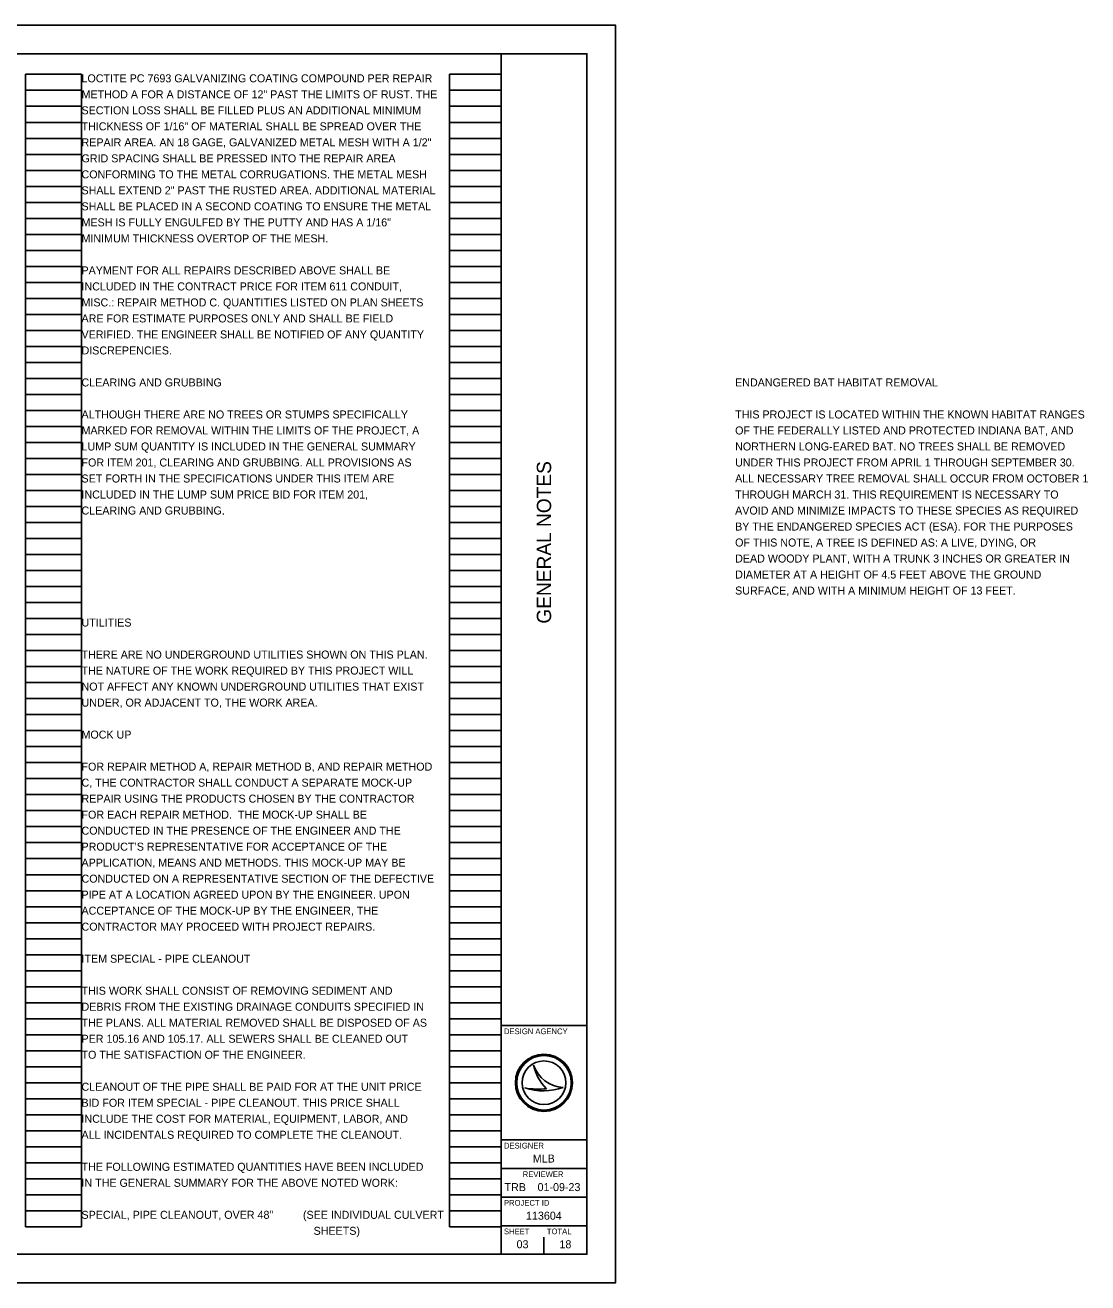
# Model space of a CAD drawing. Extents: x 0 to 42.3, y -7.4 to 22.
# Drawn here: x 23.67 to 42.26, y 0 to 22 of the extents above; entities that cross this region are included whole.
import ezdxf

# ---------------------------------------------------------------- set-up
doc = ezdxf.new("R2010")
doc.units = 0
for name, color, linetype in [('SH_Border', 7, 'Continuous'), ('SH_Cut_Line', 7, 'Continuous'), ('SH_Data', 7, 'Continuous'), ('SH_Text', 7, 'Continuous')]:
    doc.layers.add(name, color=color, linetype=linetype)

msp = doc.modelspace()

# ---------------------------------------------------------------- linework, layer by layer
at = {"layer": 'SH_Border'}
for p, q in [((32, 0.5), (32, 21.5)), ((32, 4.5), (33.5, 4.5)), ((32, 2.5), (33.5, 2.5)), ((32, 2), (33.5, 2)), ((32, 1.5), (33.5, 1.5)), ((32, 1), (33.5, 1))]:
    msp.add_line(p, q, dxfattribs=at)
msp.add_lwpolyline([(1.5, 21.5), (33.5, 21.5), (33.5, 0.5), (1.5, 0.5)], close=True, dxfattribs=at)
at = {"layer": 'SH_Cut_Line'}
msp.add_lwpolyline([(0, 0), (34, 0), (34, 22), (0, 22)], close=True, dxfattribs=at)
at = {"layer": 'SH_Data'}
for p, q in [((23.68, 0.98), (23.68, 21.14)), ((23.68, 21.14), (24.66, 21.14)), ((24.66, 0.98), (24.66, 21.14)), ((31.1, 0.98), (31.1, 21.14)), ((31.1, 21.14), (32, 21.14)), ((32, 0.98), (32, 21.14)), ((23.68, 20.86), (24.66, 20.86)), ((31.1, 20.86), (32, 20.86)), ((23.68, 20.58), (24.66, 20.58)), ((31.1, 20.58), (32, 20.58)), ((23.68, 20.3), (24.66, 20.3)), ((31.1, 20.3), (32, 20.3)), ((23.68, 20.02), (24.66, 20.02)), ((31.1, 20.02), (32, 20.02)), ((23.68, 19.74), (24.66, 19.74)), ((31.1, 19.74), (32, 19.74)), ((23.68, 19.46), (24.66, 19.46)), ((31.1, 19.46), (32, 19.46)), ((23.68, 19.18), (24.66, 19.18)), ((31.1, 19.18), (32, 19.18)), ((23.68, 18.9), (24.66, 18.9)), ((31.1, 18.9), (32, 18.9)), ((23.68, 18.62), (24.66, 18.62)), ((31.1, 18.62), (32, 18.62)), ((23.68, 18.34), (24.66, 18.34)), ((31.1, 18.34), (32, 18.34)), ((23.68, 18.06), (24.66, 18.06)), ((31.1, 18.06), (32, 18.06)), ((23.68, 17.78), (24.66, 17.78)), ((31.1, 17.78), (32, 17.78)), ((23.68, 17.5), (24.66, 17.5)), ((31.1, 17.5), (32, 17.5)), ((23.68, 17.22), (24.66, 17.22)), ((31.1, 17.22), (32, 17.22)), ((23.68, 16.94), (24.66, 16.94)), ((31.1, 16.94), (32, 16.94)), ((23.68, 16.66), (24.66, 16.66)), ((31.1, 16.66), (32, 16.66)), ((23.68, 16.38), (24.66, 16.38)), ((31.1, 16.38), (32, 16.38)), ((23.68, 16.1), (24.66, 16.1)), ((31.1, 16.1), (32, 16.1)), ((23.68, 15.82), (24.66, 15.82)), ((31.1, 15.82), (32, 15.82)), ((23.68, 15.54), (24.66, 15.54)), ((31.1, 15.54), (32, 15.54)), ((23.68, 15.26), (24.66, 15.26)), ((31.1, 15.26), (32, 15.26)), ((23.68, 14.98), (24.66, 14.98)), ((31.1, 14.98), (32, 14.98)), ((23.68, 14.7), (24.66, 14.7)), ((31.1, 14.7), (32, 14.7)), ((23.68, 14.42), (24.66, 14.42)), ((31.1, 14.42), (32, 14.42)), ((23.68, 14.14), (24.66, 14.14)), ((31.1, 14.14), (32, 14.14)), ((23.68, 13.86), (24.66, 13.86)), ((31.1, 13.86), (32, 13.86)), ((23.68, 13.58), (24.66, 13.58)), ((31.1, 13.58), (32, 13.58)), ((23.68, 13.3), (24.66, 13.3)), ((31.1, 13.3), (32, 13.3)), ((23.68, 13.02), (24.66, 13.02)), ((31.1, 13.02), (32, 13.02)), ((23.68, 12.74), (24.66, 12.74)), ((31.1, 12.74), (32, 12.74)), ((23.68, 12.46), (24.66, 12.46)), ((31.1, 12.46), (32, 12.46)), ((23.68, 12.18), (24.66, 12.18)), ((31.1, 12.18), (32, 12.18)), ((23.68, 11.9), (24.66, 11.9)), ((31.1, 11.9), (32, 11.9)), ((23.68, 11.62), (24.66, 11.62)), ((31.1, 11.62), (32, 11.62)), ((23.68, 11.34), (24.66, 11.34)), ((31.1, 11.34), (32, 11.34)), ((23.68, 11.06), (24.66, 11.06)), ((31.1, 11.06), (32, 11.06)), ((23.68, 10.78), (24.66, 10.78)), ((31.1, 10.78), (32, 10.78)), ((23.68, 10.5), (24.66, 10.5)), ((31.1, 10.5), (32, 10.5)), ((23.68, 10.22), (24.66, 10.22)), ((31.1, 10.22), (32, 10.22)), ((23.68, 9.94), (24.66, 9.94)), ((31.1, 9.94), (32, 9.94)), ((23.68, 9.66), (24.66, 9.66)), ((31.1, 9.66), (32, 9.66)), ((23.68, 9.38), (24.66, 9.38)), ((31.1, 9.38), (32, 9.38)), ((23.68, 9.1), (24.66, 9.1)), ((31.1, 9.1), (32, 9.1)), ((23.68, 8.82), (24.66, 8.82)), ((31.1, 8.82), (32, 8.82)), ((23.68, 8.54), (24.66, 8.54)), ((31.1, 8.54), (32, 8.54)), ((23.68, 8.26), (24.66, 8.26)), ((31.1, 8.26), (32, 8.26)), ((23.68, 7.98), (24.66, 7.98)), ((31.1, 7.98), (32, 7.98)), ((23.68, 7.7), (24.66, 7.7)), ((31.1, 7.7), (32, 7.7)), ((23.68, 7.42), (24.66, 7.42)), ((31.1, 7.42), (32, 7.42)), ((23.68, 7.14), (24.66, 7.14)), ((31.1, 7.14), (32, 7.14)), ((23.68, 6.86), (24.66, 6.86)), ((31.1, 6.86), (32, 6.86)), ((23.68, 6.58), (24.66, 6.58)), ((31.1, 6.58), (32, 6.58)), ((23.68, 6.3), (24.66, 6.3)), ((31.1, 6.3), (32, 6.3)), ((23.68, 6.02), (24.66, 6.02)), ((31.1, 6.02), (32, 6.02)), ((23.68, 5.74), (24.66, 5.74)), ((31.1, 5.74), (32, 5.74)), ((23.68, 5.46), (24.66, 5.46)), ((31.1, 5.46), (32, 5.46)), ((23.68, 5.18), (24.66, 5.18)), ((31.1, 5.18), (32, 5.18)), ((23.68, 4.9), (24.66, 4.9)), ((31.1, 4.9), (32, 4.9)), ((23.68, 4.62), (24.66, 4.62)), ((31.1, 4.62), (32, 4.62)), ((23.68, 4.34), (24.66, 4.34)), ((31.1, 4.34), (32, 4.34)), ((23.68, 4.06), (24.66, 4.06)), ((31.1, 4.06), (32, 4.06)), ((23.68, 3.78), (24.66, 3.78)), ((31.1, 3.78), (32, 3.78)), ((32.567, 3.81), (32.567, 3.81)), ((23.68, 3.5), (24.66, 3.5)), ((31.1, 3.5), (32, 3.5)), ((32.417, 3.41), (32.417, 3.41)), ((32.75, 3.5), (32.75, 3.5)), ((33.087, 3.419), (33.087, 3.419)), ((23.68, 3.22), (24.66, 3.22)), ((31.1, 3.22), (32, 3.22)), ((23.68, 2.94), (24.66, 2.94)), ((31.1, 2.94), (32, 2.94)), ((23.68, 2.66), (24.66, 2.66)), ((31.1, 2.66), (32, 2.66)), ((23.68, 2.38), (24.66, 2.38)), ((31.1, 2.38), (32, 2.38)), ((23.68, 2.1), (24.66, 2.1)), ((31.1, 2.1), (32, 2.1)), ((23.68, 1.82), (24.66, 1.82)), ((31.1, 1.82), (32, 1.82)), ((23.68, 1.54), (24.66, 1.54)), ((31.1, 1.54), (32, 1.54)), ((23.68, 1.26), (24.66, 1.26)), ((31.1, 1.26), (32, 1.26)), ((23.68, 0.98), (24.66, 0.98)), ((31.1, 0.98), (32, 0.98)), ((32.375, 0.675), (32.375, 0.675)), ((32.75, 0.5), (32.75, 0.8))]:
    msp.add_line(p, q, dxfattribs=at)
for radius in [0.5, 0.477, 0.477, 0.382]:
    msp.add_circle((32.75, 3.5), radius, dxfattribs=at)
for centre, radius, start, end in [((33.116, 3.998), 0.58, 198.9257, 198.9319), ((33.347, 3.97), 0.796, 191.6379, 191.6421), ((33.116, 3.998), 0.58, 198.9319, 267.1657), ((33.347, 3.97), 0.796, 191.6421, 226.0947), ((32.739, 4.37), 1.013, 251.4576, 290.0832), ((32.648, 4.654), 1.266, 259.4964, 259.4995), ((32.739, 4.37), 1.013, 251.4527, 251.4576), ((32.648, 4.654), 1.266, 259.4995, 276.6672)]:
    msp.add_arc(centre, radius, start, end, dxfattribs=at)

# ---------------------------------------------------------------- texts
msp.add_text('GENERAL NOTES', height=0.25, rotation=90, dxfattribs=at).set_placement((32.875, 11.531))
for s, height, p in [('DESIGN AGENCY', 0.1, (32.05, 4.35)), ('DESIGNER', 0.1, (32.05, 2.35)), ('MLB', 0.14, (32.554, 2.105)), ('REVIEWER', 0.1, (32.378, 1.85)), ('TRB', 0.14, (32.06, 1.605)), ('01-09-23', 0.14, (32.638, 1.605)), ('PROJECT ID', 0.1, (32.05, 1.35)), ('113604', 0.14, (32.436, 1.105)), ('SHEET', 0.1, (32.05, 0.85)), ('TOTAL', 0.1, (32.8, 0.85)), ('03', 0.14, (32.271, 0.605)), ('18', 0.14, (33.021, 0.605))]:
    msp.add_text(s, height=height, dxfattribs=at).set_placement(p)
at = {"layer": 'SH_Text'}
for s, p in [('LOCTITE PC 7693 GALVANIZING COATING COMPOUND PER REPAIR ', (24.66, 21)), ('METHOD A FOR A DISTANCE OF 12" PAST THE LIMITS OF RUST. THE ', (24.66, 20.72)), ('SECTION LOSS SHALL BE FILLED PLUS AN ADDITIONAL MINIMUM ', (24.66, 20.44)), ('THICKNESS OF 1/16" OF MATERIAL SHALL BE SPREAD OVER THE ', (24.66, 20.16)), ('REPAIR AREA. AN 18 GAGE, GALVANIZED METAL MESH WITH A 1/2" ', (24.66, 19.88)), ('GRID SPACING SHALL BE PRESSED INTO THE REPAIR AREA ', (24.66, 19.6)), ('CONFORMING TO THE METAL CORRUGATIONS. THE METAL MESH ', (24.66, 19.32)), ('SHALL EXTEND 2" PAST THE RUSTED AREA. ADDITIONAL MATERIAL ', (24.66, 19.04)), ('SHALL BE PLACED IN A SECOND COATING TO ENSURE THE METAL ', (24.66, 18.76)), ('MESH IS FULLY ENGULFED BY THE PUTTY AND HAS A 1/16" ', (24.66, 18.48)), ('MINIMUM THICKNESS OVERTOP OF THE MESH.', (24.66, 18.2)), ('PAYMENT FOR ALL REPAIRS DESCRIBED ABOVE SHALL BE ', (24.66, 17.64)), ('INCLUDED IN THE CONTRACT PRICE FOR ITEM 611 CONDUIT, ', (24.66, 17.36)), ('MISC.: REPAIR METHOD C. QUANTITIES LISTED ON PLAN SHEETS ', (24.66, 17.08)), ('ARE FOR ESTIMATE PURPOSES ONLY AND SHALL BE FIELD ', (24.66, 16.8)), ('VERIFIED. THE ENGINEER SHALL BE NOTIFIED OF ANY QUANTITY ', (24.66, 16.52)), ('DISCREPENCIES.', (24.66, 16.24)), ('CLEARING AND GRUBBING', (24.66, 15.68)), ('ENDANGERED BAT HABITAT REMOVAL', (36.094, 15.68)), ('ALTHOUGH THERE ARE NO TREES OR STUMPS SPECIFICALLY', (24.66, 15.12)), ('THIS PROJECT IS LOCATED WITHIN THE KNOWN HABITAT RANGES', (36.094, 15.12)), ('MARKED FOR REMOVAL WITHIN THE LIMITS OF THE PROJECT, A', (24.66, 14.84)), ('OF THE FEDERALLY LISTED AND PROTECTED INDIANA BAT, AND', (36.094, 14.84)), ('LUMP SUM QUANTITY IS INCLUDED IN THE GENERAL SUMMARY', (24.66, 14.56)), ('NORTHERN LONG-EARED BAT. NO TREES SHALL BE REMOVED', (36.094, 14.56)), ('FOR ITEM 201, CLEARING AND GRUBBING. ALL PROVISIONS AS', (24.66, 14.28)), ('UNDER THIS PROJECT FROM APRIL 1 THROUGH SEPTEMBER 30.', (36.094, 14.28)), ('SET FORTH IN THE SPECIFICATIONS UNDER THIS ITEM ARE', (24.66, 14)), ('ALL NECESSARY TREE REMOVAL SHALL OCCUR FROM OCTOBER 1 ', (36.094, 14)), ('INCLUDED IN THE LUMP SUM PRICE BID FOR ITEM 201, ', (24.66, 13.72)), ('THROUGH MARCH 31. THIS REQUIREMENT IS NECESSARY TO', (36.094, 13.72)), ('CLEARING AND GRUBBING.', (24.66, 13.44)), ('AVOID AND MINIMIZE IMPACTS TO THESE SPECIES AS REQUIRED', (36.094, 13.44)), ('BY THE ENDANGERED SPECIES ACT (ESA). FOR THE PURPOSES', (36.094, 13.16)), ('OF THIS NOTE, A TREE IS DEFINED AS: A LIVE, DYING, OR', (36.094, 12.88)), ('DEAD WOODY PLANT, WITH A TRUNK 3 INCHES OR GREATER IN', (36.094, 12.6)), ('DIAMETER AT A HEIGHT OF 4.5 FEET ABOVE THE GROUND', (36.094, 12.32)), ('SURFACE, AND WITH A MINIMUM HEIGHT OF 13 FEET.', (36.094, 12.04)), ('UTILITIES', (24.66, 11.48)), ('THERE ARE NO UNDERGROUND UTILITIES SHOWN ON THIS PLAN.', (24.66, 10.92)), ('THE NATURE OF THE WORK REQUIRED BY THIS PROJECT WILL', (24.66, 10.64)), ('NOT AFFECT ANY KNOWN UNDERGROUND UTILITIES THAT EXIST', (24.66, 10.36)), ('UNDER, OR ADJACENT TO, THE WORK AREA.', (24.66, 10.08)), ('MOCK UP', (24.66, 9.52)), ('FOR REPAIR METHOD A, REPAIR METHOD B, AND REPAIR METHOD ', (24.66, 8.96)), ('C, THE CONTRACTOR SHALL CONDUCT A SEPARATE MOCK-UP ', (24.66, 8.68)), ('REPAIR USING THE PRODUCTS CHOSEN BY THE CONTRACTOR ', (24.66, 8.4)), ('FOR EACH REPAIR METHOD.  THE MOCK-UP SHALL BE ', (24.66, 8.12)), ('CONDUCTED IN THE PRESENCE OF THE ENGINEER AND THE ', (24.66, 7.84)), ('PRODUCT’S REPRESENTATIVE FOR ACCEPTANCE OF THE ', (24.66, 7.56)), ('APPLICATION, MEANS AND METHODS. THIS MOCK-UP MAY BE ', (24.66, 7.28)), ('CONDUCTED ON A REPRESENTATIVE SECTION OF THE DEFECTIVE ', (24.66, 7)), ('PIPE AT A LOCATION AGREED UPON BY THE ENGINEER. UPON ', (24.66, 6.72)), ('ACCEPTANCE OF THE MOCK-UP BY THE ENGINEER, THE ', (24.66, 6.44)), ('CONTRACTOR MAY PROCEED WITH PROJECT REPAIRS. ', (24.66, 6.16)), ('ITEM SPECIAL - PIPE CLEANOUT', (24.66, 5.6)), ('THIS WORK SHALL CONSIST OF REMOVING SEDIMENT AND', (24.66, 5.04)), ('DEBRIS FROM THE EXISTING DRAINAGE CONDUITS SPECIFIED IN', (24.66, 4.76)), ('THE PLANS. ALL MATERIAL REMOVED SHALL BE DISPOSED OF AS', (24.66, 4.48)), ('PER 105.16 AND 105.17. ALL SEWERS SHALL BE CLEANED OUT', (24.66, 4.2)), ('TO THE SATISFACTION OF THE ENGINEER.', (24.66, 3.92)), ('CLEANOUT OF THE PIPE SHALL BE PAID FOR AT THE UNIT PRICE', (24.66, 3.36)), ('BID FOR ITEM SPECIAL - PIPE CLEANOUT. THIS PRICE SHALL', (24.66, 3.08)), ('INCLUDE THE COST FOR MATERIAL, EQUIPMENT, LABOR, AND', (24.66, 2.8)), ('ALL INCIDENTALS REQUIRED TO COMPLETE THE CLEANOUT.', (24.66, 2.52)), ('THE FOLLOWING ESTIMATED QUANTITIES HAVE BEEN INCLUDED', (24.66, 1.96)), ('IN THE GENERAL SUMMARY FOR THE ABOVE NOTED WORK:', (24.66, 1.68)), ('SPECIAL, PIPE CLEANOUT, OVER 48"          (SEE INDIVIDUAL CULVERT ', (24.66, 1.12)), ('SHEETS)', (28.72, 0.84))]:
    msp.add_text(s, height=0.14, dxfattribs=at).set_placement(p)

doc.saveas('drawing.dxf')
